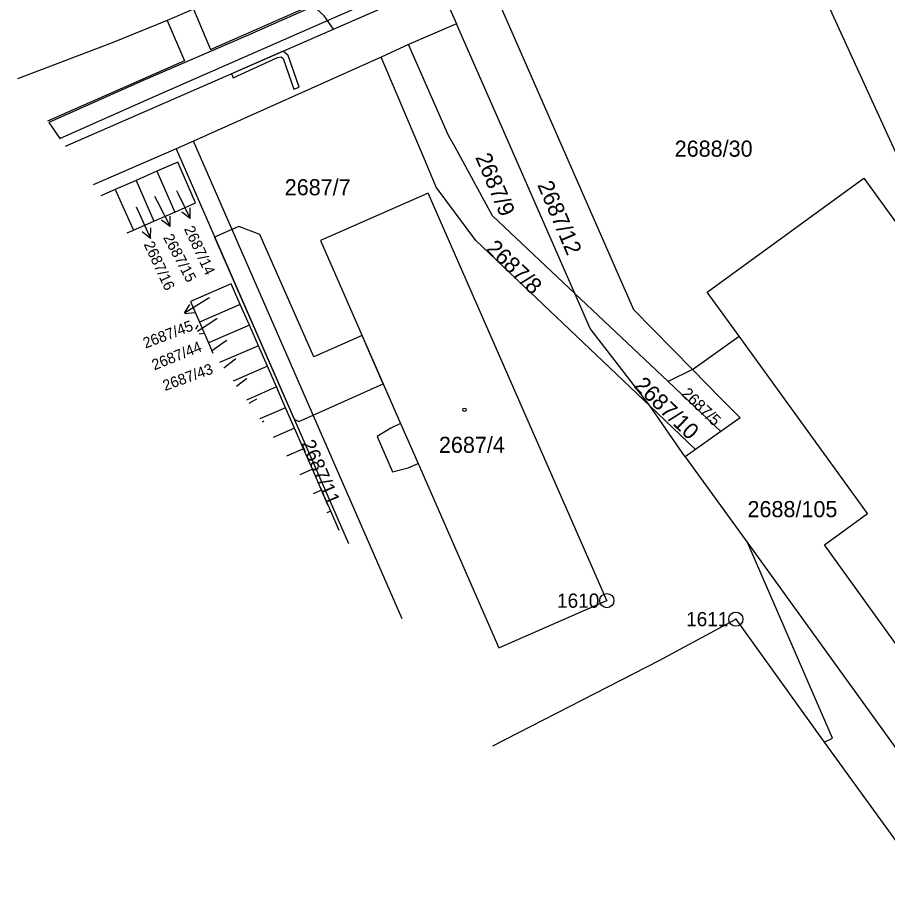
# Model space of a CAD drawing. Extents: x -821458 to -820266, y -1071458 to -1069826.
# Drawn here: x -820729.5 to -820637.8, y -1071458.4 to -1071365.5 of the extents above; entities that cross this region are included whole.
import ezdxf

# ---------------------------------------------------------------- set-up
doc = ezdxf.new("R2010")
doc.units = 0
for name, color, linetype in [('Vrstva 1', 7, 'Continuous'), ('Vrstva 13', 7, 'Continuous'), ('Vrstva 2', 7, 'Continuous'), ('Vrstva 4', 7, 'Continuous'), ('Vrstva 5', 7, 'Continuous'), ('Vrstva 7', 7, 'Continuous'), ('Vrstva 8', 7, 'Continuous')]:
    doc.layers.add(name, color=color, linetype=linetype)

msp = doc.modelspace()

# ---------------------------------------------------------------- linework, layer by layer
at = {"layer": 'Vrstva 1'}
for p, q in [((-820636.39, -1071380.88), (-820651.69, -1071347.4)), ((-820685.14, -1071361.85), (-820683.26, -1071366.16)), ((-820724.478, -1071379.063), (-820696.22, -1071366.7)), ((-820683.26, -1071366.16), (-820688.31, -1071368.34)), ((-820688.31, -1071368.34), (-820691.18, -1071369.66)), ((-820691.18, -1071369.66), (-820711, -1071378.51)), ((-820711, -1071378.51), (-820712.83, -1071379.32)), ((-820688.979, -1071428.877), (-820711, -1071378.51)), ((-820712.83, -1071379.32), (-820721.579, -1071383.13)), ((-820712.83, -1071379.32), (-820694.623, -1071420.957)), ((-820714.87, -1071381.7), (-820717.03, -1071382.67)), ((-820714.87, -1071381.7), (-820712.97, -1071386.01)), ((-820717.03, -1071382.67), (-820719.24, -1071383.62)), ((-820717.03, -1071382.67), (-820715.16, -1071386.96)), ((-820719.24, -1071383.62), (-820720.75, -1071384.294)), ((-820719.24, -1071383.62), (-820717.33, -1071387.92)), ((-820715.16, -1071386.96), (-820712.97, -1071386.01)), ((-820717.33, -1071387.92), (-820715.16, -1071386.96)), ((-820717.97, -1071388.194), (-820717.33, -1071387.92)), ((-820660.94, -1071403.88), (-820670.76, -1071394.6)), ((-820706.06, -1071395.73), (-820710.37, -1071397.59)), ((-820705.09, -1071397.92), (-820706.06, -1071395.73)), ((-820710.37, -1071397.59), (-820709.41, -1071399.79)), ((-820705.09, -1071397.92), (-820709.41, -1071399.79)), ((-820704.13, -1071400.1), (-820705.09, -1071397.92)), ((-820658.36, -1071402.6), (-820653.43, -1071399.1)), ((-820709.41, -1071399.79), (-820708.937, -1071400.871)), ((-820704.13, -1071400.1), (-820708.231, -1071401.862)), ((-820703.2, -1071402.26), (-820704.13, -1071400.1)), ((-820703.2, -1071402.26), (-820706.821, -1071403.84)), ((-820702.24, -1071404.44), (-820703.2, -1071402.26)), ((-820658.36, -1071402.6), (-820660.94, -1071403.88)), ((-820660.94, -1071403.88), (-820655.37, -1071409.15)), ((-820702.24, -1071404.44), (-820705.409, -1071405.822)), ((-820701.29, -1071406.64), (-820702.24, -1071404.44)), ((-820701.29, -1071406.64), (-820704.007, -1071407.788)), ((-820700.33, -1071408.8), (-820701.29, -1071406.64)), ((-820659.12, -1071411.82), (-820662.83, -1071406.48)), ((-820700.33, -1071408.8), (-820702.585, -1071409.784)), ((-820699.38, -1071410.98), (-820700.33, -1071408.8)), ((-820655.37, -1071409.15), (-820658.04, -1071411.05)), ((-820699.38, -1071410.98), (-820701.183, -1071411.752)), ((-820698.44, -1071413.12), (-820699.38, -1071410.98)), ((-820658.04, -1071411.05), (-820659.12, -1071411.82)), ((-820659.12, -1071411.82), (-820652.54, -1071420.92)), ((-820698.44, -1071413.12), (-820699.786, -1071413.712)), ((-820697.48, -1071415.32), (-820698.44, -1071413.12)), ((-820697.48, -1071415.32), (-820698.367, -1071415.704)), ((-820696.51, -1071417.52), (-820697.48, -1071415.32)), ((-820696.51, -1071417.52), (-820696.941, -1071417.704)), ((-820695.618, -1071419.561), (-820696.51, -1071417.52)), ((-820652.54, -1071420.92), (-820634.93, -1071445.29)), ((-820644.49, -1071441.9), (-820632.542, -1071458.368))]:
    msp.add_line(p, q, dxfattribs=at)
for points in [[(-820629.87, -1071337.4), (-820630.92, -1071336.63), (-820633.66, -1071335.41), (-820636.65, -1071334.85), (-820639.5, -1071334.97), (-820642.22, -1071335.6), (-820646.76, -1071337.17), (-820651.91, -1071339.71), (-820660.24, -1071345.49), (-820688.88, -1071358.16), (-820705.99, -1071362.63), (-820707.35, -1071363.11), (-820711, -1071364.62), (-820713.77, -1071365.79), (-820719.56, -1071368.14), (-820729.538, -1071371.963)], [(-820680.54, -1071359.84), (-820664.58, -1071396.26), (-820658.36, -1071402.6)], [(-820696.22, -1071366.7), (-820689.12, -1071363.59), (-820685.14, -1071361.85)], [(-820670.76, -1071394.6), (-820678.52, -1071376.95), (-820683.26, -1071366.16)], [(-820670.76, -1071394.6), (-820679.46, -1071386.38), (-820683.44, -1071379.09), (-820684.08, -1071377.91), (-820688.31, -1071368.34)], [(-820662.83, -1071406.48), (-820681.21, -1071388.99), (-820685.39, -1071383.38), (-820686.63, -1071380.42), (-820691.18, -1071369.66)], [(-820712.97, -1071386.01), (-820710.77, -1071385.01), (-820712.64, -1071380.75), (-820714.87, -1071381.7)], [(-820653.43, -1071399.1), (-820656.81, -1071394.43), (-820640.28, -1071382.43), (-820636.76, -1071387.29)], [(-820667.4, -1071426.97), (-820686.24, -1071384.02), (-820697.6, -1071388.98), (-820689.14, -1071408.3), (-820690.19, -1071408.77), (-820691.63, -1071409.66), (-820690, -1071413.38), (-820688.35, -1071412.98), (-820687.29, -1071412.52), (-820678.79, -1071431.95), (-820667.4, -1071426.97)], [(-820636.76, -1071387.29), (-820609.95, -1071424.33), (-820631.03, -1071439.67), (-820644.44, -1071421.08), (-820639.9, -1071417.79), (-820653.43, -1071399.1)], [(-820706.06, -1071395.73), (-820707, -1071393.58), (-820711.32, -1071395.43), (-820710.37, -1071397.59)], [(-820662.83, -1071406.48), (-820669.15, -1071398.29), (-820670.76, -1071394.6)], [(-820658.36, -1071402.6), (-820655.44, -1071405.57), (-820653.34, -1071407.7), (-820655.37, -1071409.15)], [(-820644.49, -1071441.9), (-820643.6, -1071441.48), (-820652.54, -1071420.92)], [(-820679.435, -1071442.27), (-820661.86, -1071433.29), (-820653.79, -1071428.92), (-820644.49, -1071441.9)]]:
    msp.add_lwpolyline(points, dxfattribs=at)
at = {"layer": 'Vrstva 13'}
msp.add_line((-820726.26, -1071376.562), (-820725.073, -1071378.228), dxfattribs=at)
for points in [[(-820626.97, -1071332.11), (-820650.32, -1071343.25), (-820661.25, -1071348.1), (-820672.22, -1071352.93), (-820683.3, -1071357.67), (-820690.24, -1071360.69), (-820705.28, -1071367.39), (-820716.31, -1071372.14), (-820726.26, -1071376.562)], [(-820725.073, -1071378.228), (-820715.51, -1071373.98), (-820693.48, -1071364.32), (-820690.23, -1071362.88), (-820689.78, -1071363.88), (-820687.95, -1071363.08), (-820688.4, -1071362.07), (-820682.5, -1071359.51), (-820671.42, -1071354.77), (-820660.45, -1071349.93), (-820649.48, -1071345.07), (-820628.03, -1071334.83)]]:
    msp.add_lwpolyline(points, dxfattribs=at)
for points in [[(-820700.41, -1071373.04), (-820699.84, -1071372.84), (-820701.02, -1071369.48), (-820701.52, -1071369.02), (-820706.99, -1071371.42), (-820706.79, -1071371.86), (-820702.12, -1071369.7), (-820701.74, -1071369.63), (-820701.54, -1071369.82)], [(-820698.31, -1071401.26), (-820704, -1071388.37), (-820706.21, -1071387.51), (-820706.93, -1071387.83), (-820708.76, -1071388.64), (-820700.36, -1071407.83), (-820699.88, -1071408.09), (-820698.37, -1071407.41), (-820690.97, -1071404.12), (-820693.21, -1071399.02)]]:
    msp.add_lwpolyline(points, close=True, dxfattribs=at)
at = {"layer": 'Vrstva 4'}
for p, q in [((-820662.83, -1071406.48), (-820658.04, -1071411.05)), ((-820689.14, -1071408.3), (-820687.29, -1071412.52))]:
    msp.add_line(p, q, dxfattribs=at)
for points in [[(-820711, -1071364.62), (-820709.18, -1071368.85), (-820698.47, -1071364.14)], [(-820696.22, -1071366.7), (-820697.22, -1071365.32), (-820698.47, -1071364.14)], [(-820713.77, -1071365.79), (-820711.92, -1071370.04), (-820726.373, -1071376.403)]]:
    msp.add_lwpolyline(points, dxfattribs=at)
at = {"layer": 'Vrstva 5'}
msp.add_circle((-820682.407, -1071406.839), 0.175, dxfattribs=at)
at = {"layer": 'Vrstva 7'}
for p, q in [((-820715.09, -1071384.32), (-820714.82, -1071384.86)), ((-820712.78, -1071383.73), (-820712.65, -1071383.99)), ((-820712.65, -1071383.99), (-820711.334, -1071386.687)), ((-820714.82, -1071384.86), (-820713.458, -1071387.534)), ((-820717.03, -1071385.45), (-820716.76, -1071386.05)), ((-820716.76, -1071386.05), (-820715.539, -1071388.792)), ((-820711.334, -1071386.687), (-820712.224, -1071386.007)), ((-820711.334, -1071386.687), (-820711.323, -1071385.568)), ((-820713.458, -1071387.534), (-820714.358, -1071386.869)), ((-820713.458, -1071387.534), (-820713.466, -1071386.414)), ((-820715.539, -1071388.792), (-820716.404, -1071388.08)), ((-820715.539, -1071388.792), (-820715.489, -1071387.673)), ((-820717.846, -1071388.369), (-820717.846, -1071388.364)), ((-820709.43, -1071395.11), (-820711.929, -1071396.672)), ((-820709.29, -1071395.03), (-820709.43, -1071395.11)), ((-820711.945, -1071396.65), (-820711.391, -1071395.745)), ((-820711.913, -1071396.694), (-820710.86, -1071396.594)), ((-820708.54, -1071397.27), (-820710.566, -1071398.585)), ((-820708.48, -1071397.23), (-820708.54, -1071397.27)), ((-820710.732, -1071398.351), (-820710.49, -1071397.939)), ((-820710.392, -1071398.829), (-820709.944, -1071398.779)), ((-820707.56, -1071399.56), (-820709.083, -1071400.666)), ((-820707.46, -1071399.49), (-820707.56, -1071399.56)), ((-820706.71, -1071401.62), (-820707.797, -1071402.47)), ((-820706.54, -1071401.48), (-820706.71, -1071401.62)), ((-820705.41, -1071403.57), (-820706.44, -1071404.375)), ((-820705.36, -1071403.53), (-820705.41, -1071403.57)), ((-820704.58, -1071405.87), (-820705.143, -1071406.195)), ((-820704.34, -1071405.73), (-820704.58, -1071405.87)), ((-820703.68, -1071408.1), (-820703.755, -1071408.143)), ((-820703.58, -1071408.04), (-820703.68, -1071408.1))]:
    msp.add_line(p, q, dxfattribs=at)
at = {"layer": 'Vrstva 8'}
for centre, radius in [((-820667.4, -1071426.97), 0.75), ((-820667.4, -1071426.97), 0.03), ((-820653.79, -1071428.92), 0.75), ((-820653.79, -1071428.92), 0.03)]:
    msp.add_circle(centre, radius, dxfattribs=at)

# ---------------------------------------------------------------- texts
at = {"layer": 'Vrstva 2'}
for s, p in [('2688/30', (-820660.238, -1071380.16)), ('2687/7', (-820701.365, -1071384.229)), ('2687/4', (-820685.105, -1071411.39)), ('2688/105', (-820652.56, -1071418.17))]:
    msp.add_text(s, height=1.7, dxfattribs=at).set_placement(p)
for s, height, rotation, p in [('2687/9', 1.7, 293, (-820681.294, -1071380.209)), ('2687/12', 1.7, 293, (-820674.752, -1071383.129)), ('2687/14', 1.139, 295, (-820712.012, -1071387.77)), ('2687/16', 1.139, 295, (-820716.262, -1071389.39)), ('2687/15', 1.139, 298, (-820714.22, -1071388.666)), ('2687/8', 1.7, 316, (-820680.248, -1071389.975)), ('2687/45', 1.139, 21, (-820716.056, -1071400.403)), ('2687/44', 1.139, 22, (-820715.11, -1071402.701)), ('2687/43', 1.139, 20, (-820713.991, -1071404.874)), ('2687/10', 1.7, 316, (-820664.611, -1071404.415)), ('2687/5', 1.2, 316, (-820659.606, -1071405.241)), ('2687/11', 1.5, 293, (-820699.673, -1071410.375))]:
    msp.add_text(s, height=height, rotation=rotation, dxfattribs=at).set_placement(p)
at = {"layer": 'Vrstva 8'}
for s, p in [('1610', (-820672.648, -1071427.72)), ('1611', (-820659.038, -1071429.669))]:
    msp.add_text(s, height=1.5, dxfattribs=at).set_placement(p)

doc.saveas('drawing.dxf')
